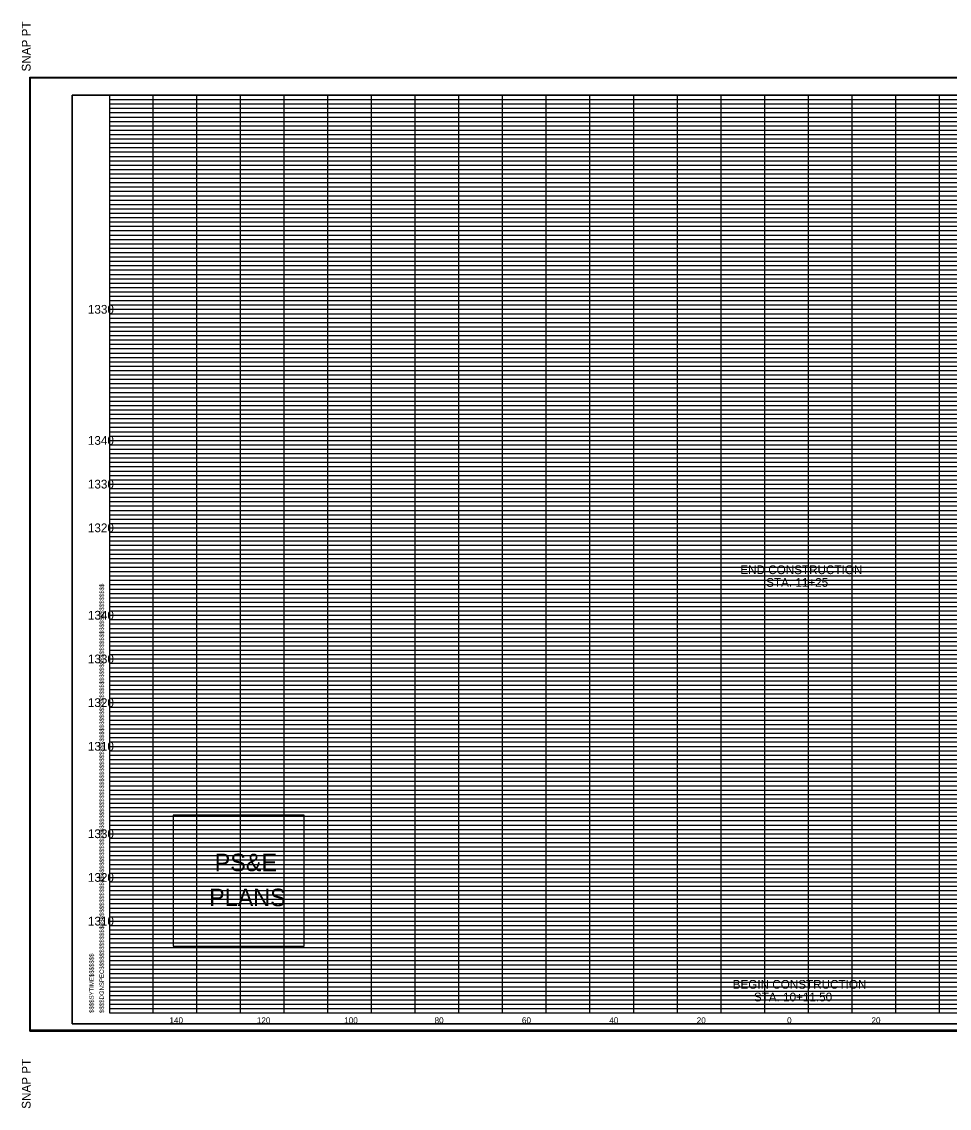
# Model space of a CAD drawing. Extents: x 980 to 1406, y 978 to 1227.
# Drawn here: x 979.9 to 1192.2, y 978.2 to 1226.8 of the extents above; entities that cross this region are included whole.
import ezdxf

# ---------------------------------------------------------------- set-up
doc = ezdxf.new("R2010")
doc.units = 0
for name, color, linetype in [('DESIGN - SHEET - Corner Text', 7, 'Continuous'), ('DESIGN - SHEET - Light Grid', 7, 'Continuous'), ('DESIGN - SHEET - Linework', 7, 'Continuous'), ('DESIGN - SHEET - Plot Shape', 7, 'Continuous'), ('DESIGN - TYPICAL - Text', 7, 'Continuous')]:
    doc.layers.add(name, color=color, linetype=linetype)

# ---------------------------------------------------------------- blocks, each defined once
blk = doc.blocks.new('XSTSHT')
at = {"layer": 'DESIGN - SHEET - Light Grid'}
for p, q in [((0, 20.9), (8, 20.9)), ((8, 20.9), (16, 20.9)), ((16, 20.9), (24, 20.9)), ((0, 20.8), (8, 20.8)), ((0, 20.7), (8, 20.7)), ((8, 20.8), (16, 20.8)), ((8, 20.7), (16, 20.7)), ((16, 20.8), (24, 20.8)), ((16, 20.7), (24, 20.7)), ((0, 20.6), (8, 20.6)), ((0, 20.5), (8, 20.5)), ((0, 20.4), (8, 20.4)), ((8, 20.6), (16, 20.6)), ((8, 20.5), (16, 20.5)), ((8, 20.4), (16, 20.4)), ((16, 20.6), (24, 20.6)), ((16, 20.5), (24, 20.5)), ((16, 20.4), (24, 20.4)), ((0, 20.3), (8, 20.3)), ((0, 20.2), (8, 20.2)), ((8, 20.3), (16, 20.3)), ((8, 20.2), (16, 20.2)), ((16, 20.3), (24, 20.3)), ((16, 20.2), (24, 20.2)), ((0, 20.1), (8, 20.1)), ((0, 19.9), (8, 19.9)), ((8, 20.1), (16, 20.1)), ((8, 19.9), (16, 19.9)), ((16, 20.1), (24, 20.1)), ((16, 19.9), (24, 19.9)), ((0, 19.8), (8, 19.8)), ((0, 19.7), (8, 19.7)), ((8, 19.8), (16, 19.8)), ((8, 19.7), (16, 19.7)), ((16, 19.8), (24, 19.8)), ((16, 19.7), (24, 19.7)), ((0, 19.6), (8, 19.6)), ((0, 19.5), (8, 19.5)), ((0, 19.4), (8, 19.4)), ((8, 19.6), (16, 19.6)), ((8, 19.5), (16, 19.5)), ((8, 19.4), (16, 19.4)), ((16, 19.6), (24, 19.6)), ((16, 19.5), (24, 19.5)), ((16, 19.4), (24, 19.4)), ((0, 19.3), (8, 19.3)), ((0, 19.2), (8, 19.2)), ((8, 19.3), (16, 19.3)), ((8, 19.2), (16, 19.2)), ((16, 19.3), (24, 19.3)), ((16, 19.2), (24, 19.2)), ((0, 19.1), (8, 19.1)), ((0, 18.9), (8, 18.9)), ((8, 19.1), (16, 19.1)), ((8, 18.9), (16, 18.9)), ((16, 19.1), (24, 19.1)), ((16, 18.9), (24, 18.9)), ((0, 18.8), (8, 18.8)), ((0, 18.7), (8, 18.7)), ((8, 18.8), (16, 18.8)), ((8, 18.7), (16, 18.7)), ((16, 18.8), (24, 18.8)), ((16, 18.7), (24, 18.7)), ((0, 18.6), (8, 18.6)), ((0, 18.5), (8, 18.5)), ((0, 18.4), (8, 18.4)), ((8, 18.6), (16, 18.6)), ((8, 18.5), (16, 18.5)), ((8, 18.4), (16, 18.4)), ((16, 18.6), (24, 18.6)), ((16, 18.5), (24, 18.5)), ((16, 18.4), (24, 18.4)), ((0, 18.3), (8, 18.3)), ((0, 18.2), (8, 18.2)), ((8, 18.3), (16, 18.3)), ((8, 18.2), (16, 18.2)), ((16, 18.3), (24, 18.3)), ((16, 18.2), (24, 18.2)), ((0, 18.1), (8, 18.1)), ((8, 18.1), (16, 18.1)), ((16, 18.1), (24, 18.1)), ((0, 17.9), (8, 17.9)), ((0, 17.8), (8, 17.8)), ((0, 17.7), (8, 17.7)), ((8, 17.9), (16, 17.9)), ((8, 17.8), (16, 17.8)), ((8, 17.7), (16, 17.7)), ((16, 17.9), (24, 17.9)), ((16, 17.8), (24, 17.8)), ((16, 17.7), (24, 17.7)), ((0, 17.6), (8, 17.6)), ((0, 17.5), (8, 17.5)), ((8, 17.6), (16, 17.6)), ((8, 17.5), (16, 17.5)), ((16, 17.6), (24, 17.6)), ((16, 17.5), (24, 17.5)), ((0, 17.4), (8, 17.4)), ((0, 17.3), (8, 17.3)), ((0, 17.2), (8, 17.2)), ((8, 17.4), (16, 17.4)), ((8, 17.3), (16, 17.3)), ((8, 17.2), (16, 17.2)), ((16, 17.4), (24, 17.4)), ((16, 17.3), (24, 17.3)), ((16, 17.2), (24, 17.2)), ((0, 17.1), (8, 17.1)), ((8, 17.1), (16, 17.1)), ((16, 17.1), (24, 17.1)), ((0, 16.9), (8, 16.9)), ((0, 16.8), (8, 16.8)), ((0, 16.7), (8, 16.7)), ((8, 16.9), (16, 16.9)), ((8, 16.8), (16, 16.8)), ((8, 16.7), (16, 16.7)), ((16, 16.9), (24, 16.9)), ((16, 16.8), (24, 16.8)), ((16, 16.7), (24, 16.7)), ((0, 16.6), (8, 16.6)), ((0, 16.5), (8, 16.5)), ((8, 16.6), (16, 16.6)), ((8, 16.5), (16, 16.5)), ((16, 16.6), (24, 16.6)), ((16, 16.5), (24, 16.5)), ((0, 16.4), (8, 16.4)), ((0, 16.3), (8, 16.3)), ((0, 16.2), (8, 16.2)), ((8, 16.4), (16, 16.4)), ((8, 16.3), (16, 16.3)), ((8, 16.2), (16, 16.2)), ((16, 16.4), (24, 16.4)), ((16, 16.3), (24, 16.3)), ((16, 16.2), (24, 16.2)), ((0, 16.1), (8, 16.1)), ((8, 16.1), (16, 16.1)), ((16, 16.1), (24, 16.1)), ((0, 15.9), (8, 15.9)), ((0, 15.8), (8, 15.8)), ((0, 15.7), (8, 15.7)), ((8, 15.9), (16, 15.9)), ((8, 15.8), (16, 15.8)), ((8, 15.7), (16, 15.7)), ((16, 15.9), (24, 15.9)), ((16, 15.8), (24, 15.8)), ((16, 15.7), (24, 15.7)), ((0, 15.6), (8, 15.6)), ((0, 15.5), (8, 15.5)), ((8, 15.6), (16, 15.6)), ((8, 15.5), (16, 15.5)), ((16, 15.6), (24, 15.6)), ((16, 15.5), (24, 15.5)), ((0, 15.4), (8, 15.4)), ((0, 15.3), (8, 15.3)), ((0, 15.2), (8, 15.2)), ((8, 15.4), (16, 15.4)), ((8, 15.3), (16, 15.3)), ((8, 15.2), (16, 15.2)), ((16, 15.4), (24, 15.4)), ((16, 15.3), (24, 15.3)), ((16, 15.2), (24, 15.2)), ((0, 15.1), (8, 15.1)), ((8, 15.1), (16, 15.1)), ((16, 15.1), (24, 15.1)), ((0, 14.9), (8, 14.9)), ((0, 14.8), (8, 14.8)), ((0, 14.7), (8, 14.7)), ((8, 14.9), (16, 14.9)), ((8, 14.8), (16, 14.8)), ((8, 14.7), (16, 14.7)), ((16, 14.9), (24, 14.9)), ((16, 14.8), (24, 14.8)), ((16, 14.7), (24, 14.7)), ((0, 14.6), (8, 14.6)), ((0, 14.5), (8, 14.5)), ((8, 14.6), (16, 14.6)), ((8, 14.5), (16, 14.5)), ((16, 14.6), (24, 14.6)), ((16, 14.5), (24, 14.5)), ((0, 14.4), (8, 14.4)), ((0, 14.3), (8, 14.3)), ((0, 14.2), (8, 14.2)), ((8, 14.4), (16, 14.4)), ((8, 14.3), (16, 14.3)), ((8, 14.2), (16, 14.2)), ((16, 14.4), (24, 14.4)), ((16, 14.3), (24, 14.3)), ((16, 14.2), (24, 14.2)), ((0, 14.1), (8, 14.1)), ((8, 14.1), (16, 14.1)), ((16, 14.1), (24, 14.1)), ((0, 13.9), (8, 13.9)), ((0, 13.8), (8, 13.8)), ((0, 13.7), (8, 13.7)), ((8, 13.9), (16, 13.9)), ((8, 13.8), (16, 13.8)), ((8, 13.7), (16, 13.7)), ((16, 13.9), (24, 13.9)), ((16, 13.8), (24, 13.8)), ((16, 13.7), (24, 13.7)), ((0, 13.6), (8, 13.6)), ((0, 13.5), (8, 13.5)), ((8, 13.6), (16, 13.6)), ((8, 13.5), (16, 13.5)), ((16, 13.6), (24, 13.6)), ((16, 13.5), (24, 13.5)), ((0, 13.4), (8, 13.4)), ((0, 13.3), (8, 13.3)), ((0, 13.2), (8, 13.2)), ((8, 13.4), (16, 13.4)), ((8, 13.3), (16, 13.3)), ((8, 13.2), (16, 13.2)), ((16, 13.4), (24, 13.4)), ((16, 13.3), (24, 13.3)), ((16, 13.2), (24, 13.2)), ((0, 13.1), (8, 13.1)), ((8, 13.1), (16, 13.1)), ((16, 13.1), (24, 13.1)), ((0, 12.9), (8, 12.9)), ((0, 12.8), (8, 12.8)), ((0, 12.7), (8, 12.7)), ((8, 12.9), (16, 12.9)), ((8, 12.8), (16, 12.8)), ((8, 12.7), (16, 12.7)), ((16, 12.9), (24, 12.9)), ((16, 12.8), (24, 12.8)), ((16, 12.7), (24, 12.7)), ((0, 12.6), (8, 12.6)), ((0, 12.5), (8, 12.5)), ((8, 12.6), (16, 12.6)), ((8, 12.5), (16, 12.5)), ((16, 12.6), (24, 12.6)), ((16, 12.5), (24, 12.5)), ((0, 12.4), (8, 12.4)), ((0, 12.3), (8, 12.3)), ((0, 12.2), (8, 12.2)), ((8, 12.4), (16, 12.4)), ((8, 12.3), (16, 12.3)), ((8, 12.2), (16, 12.2)), ((16, 12.4), (24, 12.4)), ((16, 12.3), (24, 12.3)), ((16, 12.2), (24, 12.2)), ((0, 12.1), (8, 12.1)), ((8, 12.1), (16, 12.1)), ((16, 12.1), (24, 12.1)), ((0, 11.9), (8, 11.9)), ((0, 11.8), (8, 11.8)), ((0, 11.7), (8, 11.7)), ((8, 11.9), (16, 11.9)), ((8, 11.8), (16, 11.8)), ((8, 11.7), (16, 11.7)), ((16, 11.9), (24, 11.9)), ((16, 11.8), (24, 11.8)), ((16, 11.7), (24, 11.7)), ((0, 11.6), (8, 11.6)), ((0, 11.5), (8, 11.5)), ((8, 11.6), (16, 11.6)), ((8, 11.5), (16, 11.5)), ((16, 11.6), (24, 11.6)), ((16, 11.5), (24, 11.5)), ((0, 11.4), (8, 11.4)), ((0, 11.3), (8, 11.3)), ((0, 11.2), (8, 11.2)), ((8, 11.4), (16, 11.4)), ((8, 11.3), (16, 11.3)), ((8, 11.2), (16, 11.2)), ((16, 11.4), (24, 11.4)), ((16, 11.3), (24, 11.3)), ((16, 11.2), (24, 11.2)), ((0, 11.1), (8, 11.1)), ((8, 11.1), (16, 11.1)), ((16, 11.1), (24, 11.1)), ((0, 10.9), (8, 10.9)), ((0, 10.8), (8, 10.8)), ((0, 10.7), (8, 10.7)), ((8, 10.9), (16, 10.9)), ((8, 10.8), (16, 10.8)), ((8, 10.7), (16, 10.7)), ((16, 10.9), (24, 10.9)), ((16, 10.8), (24, 10.8)), ((16, 10.7), (24, 10.7)), ((0, 10.6), (8, 10.6)), ((0, 10.5), (8, 10.5)), ((8, 10.6), (16, 10.6)), ((8, 10.5), (16, 10.5)), ((16, 10.6), (24, 10.6)), ((16, 10.5), (24, 10.5)), ((0, 10.4), (8, 10.4)), ((0, 10.3), (8, 10.3)), ((0, 10.2), (8, 10.2)), ((8, 10.4), (16, 10.4)), ((8, 10.3), (16, 10.3)), ((8, 10.2), (16, 10.2)), ((16, 10.4), (24, 10.4)), ((16, 10.3), (24, 10.3)), ((16, 10.2), (24, 10.2)), ((0, 10.1), (8, 10.1)), ((8, 10.1), (16, 10.1)), ((16, 10.1), (24, 10.1)), ((0, 9.9), (8, 9.9)), ((0, 9.8), (8, 9.8)), ((0, 9.7), (8, 9.7)), ((8, 9.9), (16, 9.9)), ((8, 9.8), (16, 9.8)), ((8, 9.7), (16, 9.7)), ((16, 9.9), (24, 9.9)), ((16, 9.8), (24, 9.8)), ((16, 9.7), (24, 9.7)), ((0, 9.6), (8, 9.6)), ((0, 9.5), (8, 9.5)), ((8, 9.6), (16, 9.6)), ((8, 9.5), (16, 9.5)), ((16, 9.6), (24, 9.6)), ((16, 9.5), (24, 9.5)), ((0, 9.4), (8, 9.4)), ((0, 9.3), (8, 9.3)), ((0, 9.2), (8, 9.2)), ((8, 9.4), (16, 9.4)), ((8, 9.3), (16, 9.3)), ((8, 9.2), (16, 9.2)), ((16, 9.4), (24, 9.4)), ((16, 9.3), (24, 9.3)), ((16, 9.2), (24, 9.2)), ((0, 9.1), (8, 9.1)), ((8, 9.1), (16, 9.1)), ((16, 9.1), (24, 9.1)), ((0, 8.9), (8, 8.9)), ((0, 8.8), (8, 8.8)), ((8, 8.9), (16, 8.9)), ((8, 8.8), (16, 8.8)), ((16, 8.9), (24, 8.9)), ((16, 8.8), (24, 8.8)), ((0, 8.7), (8, 8.7)), ((0, 8.6), (8, 8.6)), ((0, 8.5), (8, 8.5)), ((8, 8.7), (16, 8.7)), ((8, 8.6), (16, 8.6)), ((8, 8.5), (16, 8.5)), ((16, 8.7), (24, 8.7)), ((16, 8.6), (24, 8.6)), ((16, 8.5), (24, 8.5)), ((0, 8.4), (8, 8.4)), ((0, 8.3), (8, 8.3)), ((8, 8.4), (16, 8.4)), ((8, 8.3), (16, 8.3)), ((16, 8.4), (24, 8.4)), ((16, 8.3), (24, 8.3)), ((0, 8.2), (8, 8.2)), ((0, 8.1), (8, 8.1)), ((8, 8.2), (16, 8.2)), ((8, 8.1), (16, 8.1)), ((16, 8.2), (24, 8.2)), ((16, 8.1), (24, 8.1)), ((0, 7.9), (8, 7.9)), ((0, 7.8), (8, 7.8)), ((8, 7.9), (16, 7.9)), ((8, 7.8), (16, 7.8)), ((16, 7.9), (24, 7.9)), ((16, 7.8), (24, 7.8)), ((0, 7.7), (8, 7.7)), ((0, 7.6), (8, 7.6)), ((0, 7.5), (8, 7.5)), ((8, 7.7), (16, 7.7)), ((8, 7.6), (16, 7.6)), ((8, 7.5), (16, 7.5)), ((16, 7.7), (24, 7.7)), ((16, 7.6), (24, 7.6)), ((16, 7.5), (24, 7.5)), ((0, 7.4), (8, 7.4)), ((0, 7.3), (8, 7.3)), ((8, 7.4), (16, 7.4)), ((8, 7.3), (16, 7.3)), ((16, 7.4), (24, 7.4)), ((16, 7.3), (24, 7.3)), ((0, 7.2), (8, 7.2)), ((0, 7.1), (8, 7.1)), ((8, 7.2), (16, 7.2)), ((8, 7.1), (16, 7.1)), ((16, 7.2), (24, 7.2)), ((16, 7.1), (24, 7.1)), ((0, 6.9), (8, 6.9)), ((0, 6.8), (8, 6.8)), ((8, 6.9), (16, 6.9)), ((8, 6.8), (16, 6.8)), ((16, 6.9), (24, 6.9)), ((16, 6.8), (24, 6.8)), ((0, 6.7), (8, 6.7)), ((0, 6.6), (8, 6.6)), ((0, 6.5), (8, 6.5)), ((8, 6.7), (16, 6.7)), ((8, 6.6), (16, 6.6)), ((8, 6.5), (16, 6.5)), ((16, 6.7), (24, 6.7)), ((16, 6.6), (24, 6.6)), ((16, 6.5), (24, 6.5)), ((0, 6.4), (8, 6.4)), ((0, 6.3), (8, 6.3)), ((8, 6.4), (16, 6.4)), ((8, 6.3), (16, 6.3)), ((16, 6.4), (24, 6.4)), ((16, 6.3), (24, 6.3)), ((0, 6.2), (8, 6.2)), ((0, 6.1), (8, 6.1)), ((8, 6.2), (16, 6.2)), ((8, 6.1), (16, 6.1)), ((16, 6.2), (24, 6.2)), ((16, 6.1), (24, 6.1)), ((0, 5.9), (8, 5.9)), ((0, 5.8), (8, 5.8)), ((8, 5.9), (16, 5.9)), ((8, 5.8), (16, 5.8)), ((16, 5.9), (24, 5.9)), ((16, 5.8), (24, 5.8)), ((0, 5.7), (8, 5.7)), ((0, 5.6), (8, 5.6)), ((0, 5.5), (8, 5.5)), ((8, 5.7), (16, 5.7)), ((8, 5.6), (16, 5.6)), ((8, 5.5), (16, 5.5)), ((16, 5.7), (24, 5.7)), ((16, 5.6), (24, 5.6)), ((16, 5.5), (24, 5.5)), ((0, 5.4), (8, 5.4)), ((0, 5.3), (8, 5.3)), ((8, 5.4), (16, 5.4)), ((8, 5.3), (16, 5.3)), ((16, 5.4), (24, 5.4)), ((16, 5.3), (24, 5.3)), ((0, 5.2), (8, 5.2)), ((0, 5.1), (8, 5.1)), ((8, 5.2), (16, 5.2)), ((8, 5.1), (16, 5.1)), ((16, 5.2), (24, 5.2)), ((16, 5.1), (24, 5.1)), ((0, 4.9), (8, 4.9)), ((0, 4.8), (8, 4.8)), ((8, 4.9), (16, 4.9)), ((8, 4.8), (16, 4.8)), ((16, 4.9), (24, 4.9)), ((16, 4.8), (24, 4.8)), ((0, 4.7), (8, 4.7)), ((0, 4.6), (8, 4.6)), ((0, 4.5), (8, 4.5)), ((8, 4.7), (16, 4.7)), ((8, 4.6), (16, 4.6)), ((8, 4.5), (16, 4.5)), ((16, 4.7), (24, 4.7)), ((16, 4.6), (24, 4.6)), ((16, 4.5), (24, 4.5)), ((0, 4.4), (8, 4.4)), ((0, 4.3), (8, 4.3)), ((8, 4.4), (16, 4.4)), ((8, 4.3), (16, 4.3)), ((16, 4.4), (24, 4.4)), ((16, 4.3), (24, 4.3)), ((0, 4.2), (8, 4.2)), ((0, 4.1), (8, 4.1)), ((8, 4.2), (16, 4.2)), ((8, 4.1), (16, 4.1)), ((16, 4.2), (24, 4.2)), ((16, 4.1), (24, 4.1)), ((0, 3.9), (8, 3.9)), ((0, 3.8), (8, 3.8)), ((8, 3.9), (16, 3.9)), ((8, 3.8), (16, 3.8)), ((16, 3.9), (24, 3.9)), ((16, 3.8), (24, 3.8)), ((0, 3.7), (8, 3.7)), ((0, 3.6), (8, 3.6)), ((0, 3.5), (8, 3.5)), ((8, 3.7), (16, 3.7)), ((8, 3.6), (16, 3.6)), ((8, 3.5), (16, 3.5)), ((16, 3.7), (24, 3.7)), ((16, 3.6), (24, 3.6)), ((16, 3.5), (24, 3.5)), ((0, 3.4), (8, 3.4)), ((0, 3.3), (8, 3.3)), ((8, 3.4), (16, 3.4)), ((8, 3.3), (16, 3.3)), ((16, 3.4), (24, 3.4)), ((16, 3.3), (24, 3.3)), ((0, 3.2), (8, 3.2)), ((0, 3.1), (8, 3.1)), ((8, 3.2), (16, 3.2)), ((8, 3.1), (16, 3.1)), ((16, 3.2), (24, 3.2)), ((16, 3.1), (24, 3.1)), ((0, 2.9), (8, 2.9)), ((0, 2.8), (8, 2.8)), ((8, 2.9), (16, 2.9)), ((8, 2.8), (16, 2.8)), ((16, 2.9), (24, 2.9)), ((16, 2.8), (24, 2.8)), ((0, 2.7), (8, 2.7)), ((0, 2.6), (8, 2.6)), ((0, 2.5), (8, 2.5)), ((8, 2.7), (16, 2.7)), ((8, 2.6), (16, 2.6)), ((8, 2.5), (16, 2.5)), ((16, 2.7), (24, 2.7)), ((16, 2.6), (24, 2.6)), ((16, 2.5), (24, 2.5)), ((0, 2.4), (8, 2.4)), ((0, 2.3), (8, 2.3)), ((8, 2.4), (16, 2.4)), ((8, 2.3), (16, 2.3)), ((16, 2.4), (24, 2.4)), ((16, 2.3), (24, 2.3)), ((0, 2.2), (8, 2.2)), ((0, 2.1), (8, 2.1)), ((8, 2.2), (16, 2.2)), ((8, 2.1), (16, 2.1)), ((16, 2.2), (24, 2.2)), ((16, 2.1), (24, 2.1)), ((0, 1.9), (8, 1.9)), ((0, 1.8), (8, 1.8)), ((8, 1.9), (16, 1.9)), ((8, 1.8), (16, 1.8)), ((16, 1.9), (24, 1.9)), ((16, 1.8), (24, 1.8)), ((0, 1.7), (8, 1.7)), ((0, 1.6), (8, 1.6)), ((0, 1.5), (8, 1.5)), ((8, 1.7), (16, 1.7)), ((8, 1.6), (16, 1.6)), ((8, 1.5), (16, 1.5)), ((16, 1.7), (24, 1.7)), ((16, 1.6), (24, 1.6)), ((16, 1.5), (24, 1.5)), ((0, 1.4), (8, 1.4)), ((0, 1.3), (8, 1.3)), ((8, 1.4), (16, 1.4)), ((8, 1.3), (16, 1.3)), ((16, 1.4), (24, 1.4)), ((16, 1.3), (24, 1.3)), ((0, 1.2), (8, 1.2)), ((0, 1.1), (8, 1.1)), ((8, 1.2), (16, 1.2)), ((8, 1.1), (16, 1.1)), ((16, 1.2), (24, 1.2)), ((16, 1.1), (24, 1.1)), ((0, 0.9), (8, 0.9)), ((0, 0.8), (8, 0.8)), ((8, 0.9), (16, 0.9)), ((8, 0.8), (16, 0.8)), ((16, 0.9), (24, 0.9)), ((16, 0.8), (24, 0.8)), ((0, 0.7), (8, 0.7)), ((0, 0.6), (8, 0.6)), ((0, 0.5), (8, 0.5)), ((8, 0.7), (16, 0.7)), ((8, 0.6), (16, 0.6)), ((8, 0.5), (16, 0.5)), ((16, 0.7), (24, 0.7)), ((16, 0.6), (24, 0.6)), ((16, 0.5), (24, 0.5)), ((0, 0.4), (8, 0.4)), ((0, 0.3), (8, 0.3)), ((8, 0.4), (16, 0.4)), ((8, 0.3), (16, 0.3)), ((16, 0.4), (24, 0.4)), ((16, 0.3), (24, 0.3)), ((0, 0.2), (8, 0.2)), ((0, 0.1), (8, 0.1)), ((8, 0.2), (16, 0.2)), ((8, 0.1), (16, 0.1)), ((16, 0.2), (24, 0.2)), ((16, 0.1), (24, 0.1))]:
    blk.add_line(p, q, dxfattribs=at)
at = {"layer": 'DESIGN - SHEET - Linework'}
for p, q in [((-1.823, -0.414), (-1.823, 21.414)), ((-1.823, 21.414), (32.217, 21.414)), ((1, 0), (1, 21)), ((2, 0), (2, 21)), ((3, 0), (3, 21)), ((4, 0), (4, 21)), ((5, 0), (5, 21)), ((6, 0), (6, 21)), ((7, 0), (7, 21)), ((8, 0), (8, 21)), ((9, 0), (9, 21)), ((10, 0), (10, 21)), ((11, 0), (11, 21)), ((12, 0), (12, 21)), ((13, 0), (13, 21)), ((14, 0), (14, 21)), ((15, 0), (15, 21)), ((16, 0), (16, 21)), ((17, 0), (17, 21)), ((18, 0), (18, 21)), ((19, 0), (19, 21)), ((0, 20), (28, 20)), ((0, 19), (32, 19)), ((0, 18), (32, 18)), ((0, 17), (32, 17)), ((0, 16), (32, 16)), ((0, 15), (32, 15)), ((0, 14), (32, 14)), ((0, 13), (32, 13)), ((0, 12), (32, 12)), ((0, 11), (32, 11)), ((0, 10), (32, 10)), ((0, 9), (32, 9)), ((0, 8), (32, 8)), ((0, 7), (32, 7)), ((0, 6), (32, 6)), ((0, 5), (32, 5)), ((0, 4), (32, 4)), ((0, 3), (32, 3)), ((0, 2), (32, 2)), ((0, 1), (32, 1)), ((-1.823, -0.414), (32.217, -0.414))]:
    blk.add_line(p, q, dxfattribs=at)
blk.add_lwpolyline([(0, 21), (0, 0), (32, 0), (32, 21), (0, 21)], dxfattribs=at)
at = {"layer": 'DESIGN - SHEET - Plot Shape'}
for points in [[(-1.803, 21.394), (32.197, 21.394), (32.197, -0.394), (-1.803, -0.394)], [(-0.85, 21), (32, 21), (32, -0.25), (-0.85, -0.25)]]:
    blk.add_lwpolyline(points, close=True, dxfattribs=at)
at = {"layer": 'DESIGN - SHEET - Corner Text'}
for s, height, p in [('  SNAP PT', 0.2, (-1.803, 21.394)), ('$$$$DGNSPEC$$$$$$$$$$$$$$$$$$$$$$$$$$$$$$$$$$$$$$$$$$$$$$$$$$$$$$$$$$$$$$$$$$$$$$$$$$$$$$$$$$$$$$$$$$$$$$$$$$$$$$$$$$$$$$$$$$$', 0.100002, (-0.126, 0)), ('$$$$SYTIME$$$$$$$', 0.1, (-0.358, 0)), ('SNAP PT  ', 0.2, (-1.803, -2.194))]:
    blk.add_text(s, height=height, rotation=90, dxfattribs=at).set_placement(p)

msp = doc.modelspace()

# ---------------------------------------------------------------- linework, layer by layer
at = {"layer": 'DESIGN - SHEET - Corner Text'}
msp.add_lwpolyline([(1014.59, 1045.25), (1014.59, 1015.25), (1044.59, 1015.25), (1044.59, 1045.25)], close=True, dxfattribs=at)
at = {"layer": 'DESIGN - SHEET - Plot Shape'}
msp.add_lwpolyline([(991.5, 997.5), (1320, 997.5), (1320, 1210), (991.5, 1210)], close=True, dxfattribs=at)

# ---------------------------------------------------------------- block references
at = {"layer": 'DESIGN - TYPICAL - Text', "xscale": 10, "yscale": 10}
msp.add_blockref('XSTSHT', (1000, 1000), dxfattribs=at)

# ---------------------------------------------------------------- texts
at = {"layer": 'DESIGN - SHEET - Corner Text'}
for s, p in [('PS&E', (1024.11, 1032.43)), ('PLANS', (1022.82, 1024.43))]:
    msp.add_text(s, height=4, dxfattribs=at).set_placement(p)
at = {"layer": 'DESIGN - TYPICAL - Text'}
for s, height, p in [('     1330     ', 2, (991.37, 1160)), ('     1340     ', 2, (991.37, 1130)), ('     1330     ', 2, (991.37, 1120)), ('     1320     ', 2, (991.37, 1110)), ('END CONSTRUCTION', 2, (1144.41, 1100.41)), ('STA. 11+25', 2, (1150.32, 1097.51)), ('     1340     ', 2, (991.37, 1090)), ('     1330     ', 2, (991.37, 1080)), ('     1320     ', 2, (991.37, 1070)), ('     1310     ', 2, (991.37, 1060)), ('     1330     ', 2, (991.37, 1040)), ('     1320     ', 2, (991.37, 1030)), ('     1310     ', 2, (991.37, 1020)), ('BEGIN CONSTRUCTION', 2, (1142.66, 1005.54)), ('STA. 10+11.50', 2, (1147.51, 1002.64)), ('     140     ', 1.4, (1011.14, 997.6)), ('     120     ', 1.4, (1031.14, 997.6)), ('     100     ', 1.4, (1051.14, 997.6)), ('     80     ', 1.4, (1071.82, 997.6)), ('     60     ', 1.4, (1091.82, 997.6)), ('     40     ', 1.4, (1111.82, 997.6)), ('     20     ', 1.4, (1131.82, 997.6)), ('     0     ', 1.4, (1152.51, 997.6)), ('     0     ', 1.4, (1152.51, 997.6)), ('     20     ', 1.4, (1171.82, 997.6))]:
    msp.add_text(s, height=height, dxfattribs=at).set_placement(p)

doc.saveas('drawing.dxf')
